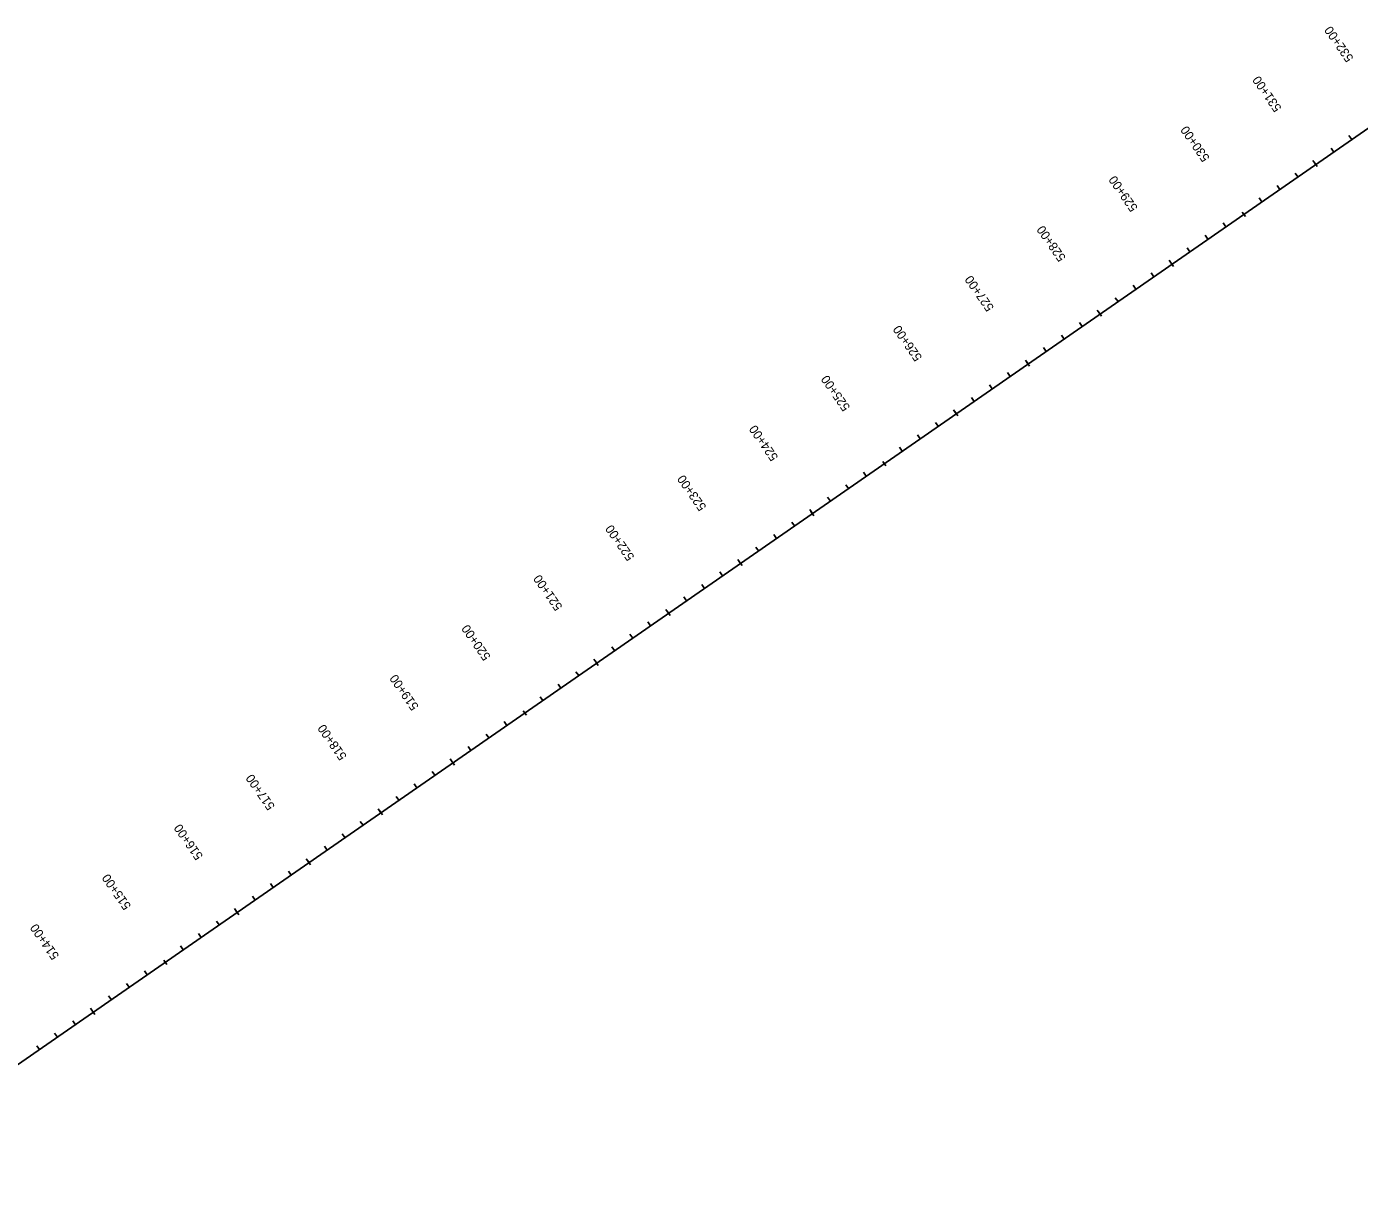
# Model space of a CAD drawing. Extents: x 11276213 to 11292489, y 9492633 to 9513914.
# Drawn here: x 11280563 to 11282086, y 9499310 to 9500632 of the extents above; entities that cross this region are included whole.
import ezdxf

# ---------------------------------------------------------------- set-up
doc = ezdxf.new("R2010")
doc.units = 0
for name, color, linetype in [('Alignment', 7, 'Continuous'), ('TextAlignment', 7, 'Continuous'), ('TextAlignmentLrg', 7, 'Continuous'), ('TextAlignmentSml', 7, 'Continuous')]:
    doc.layers.add(name, color=color, linetype=linetype)

msp = doc.modelspace()

# ---------------------------------------------------------------- linework, layer by layer
at = {"layer": 'Alignment'}
msp.add_line((11280357.5, 9499309.8), (11282134.5, 9500542.6), dxfattribs=at)
at = {"layer": 'TextAlignment'}
msp.add_line((11280357.5, 9499309.8), (11282134.5, 9500542.6), dxfattribs=at)
at = {"layer": 'TextAlignmentLrg'}
for p, q in [((11282036.3, 9500474.4), (11282033.1, 9500478.9)), ((11281952.3, 9500419.9), (11281955.8, 9500414.9)), ((11281871.9, 9500360.4), (11281868.8, 9500364.9)), ((11281789.8, 9500303.4), (11281786.6, 9500307.9)), ((11281707.6, 9500246.4), (11281704.5, 9500250.9)), ((11281625.4, 9500189.4), (11281622.3, 9500193.9)), ((11281541.5, 9500134.9), (11281545, 9500129.9)), ((11281461.1, 9500075.4), (11281458, 9500079.9)), ((11281378.9, 9500018.4), (11281375.8, 9500022.9)), ((11281296.8, 9499961.4), (11281293.6, 9499965.9)), ((11281214.6, 9499904.4), (11281211.5, 9499908.9)), ((11281130.7, 9499849.9), (11281134.2, 9499844.9)), ((11281050.3, 9499790.4), (11281047.2, 9499794.9)), ((11280968.1, 9499733.4), (11280965, 9499737.9)), ((11280885.9, 9499676.4), (11280882.8, 9499680.9)), ((11280803.8, 9499619.4), (11280800.7, 9499623.9)), ((11280719.9, 9499564.9), (11280723.3, 9499559.9)), ((11280639.4, 9499505.4), (11280636.3, 9499509.9))]:
    msp.add_line(p, q, dxfattribs=at)
at = {"layer": 'TextAlignmentSml'}
for p, q in [((11282077.3, 9500502.9), (11282074.2, 9500507.4)), ((11282056.8, 9500488.6), (11282053.7, 9500493.1)), ((11282034.5, 9500476.9), (11282038, 9500471.9)), ((11282015.7, 9500460.1), (11282012.6, 9500464.6)), ((11281995.2, 9500445.9), (11281992.1, 9500450.4)), ((11281974.6, 9500431.6), (11281971.5, 9500436.1)), ((11281952.3, 9500419.9), (11281955.8, 9500414.9)), ((11281933.5, 9500403.1), (11281930.4, 9500407.6)), ((11281913, 9500388.9), (11281909.9, 9500393.4)), ((11281892.5, 9500374.6), (11281889.3, 9500379.1)), ((11281870.2, 9500362.9), (11281873.7, 9500357.9)), ((11281851.4, 9500346.1), (11281848.3, 9500350.6)), ((11281830.8, 9500331.9), (11281827.7, 9500336.4)), ((11281810.3, 9500317.6), (11281807.2, 9500322.1)), ((11281769.2, 9500289.1), (11281766.1, 9500293.6)), ((11281788, 9500305.9), (11281791.5, 9500300.9)), ((11281748.7, 9500274.9), (11281745.6, 9500279.4)), ((11281728.1, 9500260.6), (11281725, 9500265.1)), ((11281705.8, 9500248.9), (11281709.3, 9500243.9)), ((11281687, 9500232.1), (11281683.9, 9500236.6)), ((11281666.5, 9500217.9), (11281663.4, 9500222.4)), ((11281646, 9500203.6), (11281642.9, 9500208.1)), ((11281623.7, 9500191.9), (11281627.2, 9500186.9)), ((11281604.9, 9500175.1), (11281601.8, 9500179.6)), ((11281584.3, 9500160.9), (11281581.2, 9500165.4)), ((11281563.8, 9500146.6), (11281560.7, 9500151.1)), ((11281541.5, 9500134.9), (11281545, 9500129.9)), ((11281522.7, 9500118.2), (11281519.6, 9500122.6)), ((11281502.2, 9500103.9), (11281499.1, 9500108.4)), ((11281481.6, 9500089.7), (11281478.5, 9500094.1)), ((11281440.5, 9500061.2), (11281437.4, 9500065.6)), ((11281459.3, 9500077.9), (11281462.8, 9500072.9)), ((11281420, 9500046.9), (11281416.9, 9500051.4)), ((11281399.5, 9500032.7), (11281396.4, 9500037.1)), ((11281377.2, 9500020.9), (11281380.7, 9500015.9)), ((11281358.4, 9500004.2), (11281355.3, 9500008.6)), ((11281337.8, 9499989.9), (11281334.7, 9499994.4)), ((11281317.3, 9499975.7), (11281314.2, 9499980.1)), ((11281295, 9499963.9), (11281298.5, 9499958.9)), ((11281276.2, 9499947.2), (11281273.1, 9499951.6)), ((11281255.7, 9499932.9), (11281252.6, 9499937.4)), ((11281235.1, 9499918.7), (11281232, 9499923.1)), ((11281212.9, 9499906.9), (11281216.3, 9499901.9)), ((11281194.1, 9499890.2), (11281190.9, 9499894.6)), ((11281173.5, 9499875.9), (11281170.4, 9499880.4)), ((11281153, 9499861.7), (11281149.9, 9499866.1)), ((11281111.9, 9499833.2), (11281108.8, 9499837.6)), ((11281130.7, 9499849.9), (11281134.2, 9499844.9)), ((11281091.3, 9499818.9), (11281088.2, 9499823.4)), ((11281070.8, 9499804.7), (11281067.7, 9499809.1)), ((11281048.5, 9499792.9), (11281052, 9499787.9)), ((11281029.7, 9499776.2), (11281026.6, 9499780.6)), ((11281009.2, 9499761.9), (11281006.1, 9499766.4)), ((11280988.6, 9499747.7), (11280985.5, 9499752.1)), ((11280966.4, 9499735.9), (11280969.8, 9499730.9)), ((11280947.6, 9499719.2), (11280944.4, 9499723.6)), ((11280927, 9499704.9), (11280923.9, 9499709.4)), ((11280906.5, 9499690.7), (11280903.4, 9499695.1)), ((11280884.2, 9499678.9), (11280887.7, 9499673.9)), ((11280865.4, 9499662.2), (11280862.3, 9499666.7)), ((11280824.3, 9499633.7), (11280821.2, 9499638.2)), ((11280844.8, 9499647.9), (11280841.7, 9499652.4)), ((11280783.2, 9499605.2), (11280780.1, 9499609.7)), ((11280802, 9499621.9), (11280805.5, 9499616.9)), ((11280762.7, 9499590.9), (11280759.6, 9499595.4)), ((11280742.1, 9499576.7), (11280739, 9499581.2)), ((11280719.9, 9499564.9), (11280723.3, 9499559.9)), ((11280701.1, 9499548.2), (11280697.9, 9499552.7)), ((11280680.5, 9499533.9), (11280677.4, 9499538.4)), ((11280660, 9499519.7), (11280656.9, 9499524.2)), ((11280637.7, 9499507.9), (11280641.2, 9499502.9)), ((11280618.9, 9499491.2), (11280615.8, 9499495.7)), ((11280598.4, 9499476.9), (11280595.2, 9499481.4)), ((11280577.8, 9499462.7), (11280574.7, 9499467.2))]:
    msp.add_line(p, q, dxfattribs=at)

# ---------------------------------------------------------------- texts
at = {"layer": 'TextAlignmentLrg'}
for s, p in [('530+00', (11281915.5, 9500481.9)), ('525+00', (11281504.7, 9500196.9)), ('520+00', (11281093.9, 9499911.9)), ('515+00', (11280683, 9499626.9))]:
    msp.add_text(s, height=10.2, rotation=124.7491, dxfattribs=at).set_placement(p)
at = {"layer": 'TextAlignmentSml'}
for s, p in [('532+00', (11282079.9, 9500595.9)), ('531+00', (11281997.7, 9500538.9)), ('530+00', (11281915.5, 9500481.9)), ('529+00', (11281833.4, 9500424.9)), ('528+00', (11281751.2, 9500367.9)), ('527+00', (11281669, 9500310.9)), ('526+00', (11281586.9, 9500253.9)), ('525+00', (11281504.7, 9500196.9)), ('524+00', (11281422.5, 9500139.9)), ('523+00', (11281340.4, 9500082.9)), ('522+00', (11281258.2, 9500025.9)), ('521+00', (11281176, 9499968.9)), ('520+00', (11281093.9, 9499911.9)), ('519+00', (11281011.7, 9499854.9)), ('518+00', (11280929.5, 9499797.9)), ('517+00', (11280847.4, 9499740.9)), ('516+00', (11280765.2, 9499683.9)), ('515+00', (11280683, 9499626.9)), ('514+00', (11280600.9, 9499569.9))]:
    msp.add_text(s, height=10.2, rotation=124.7491, dxfattribs=at).set_placement(p)

doc.saveas('drawing.dxf')
